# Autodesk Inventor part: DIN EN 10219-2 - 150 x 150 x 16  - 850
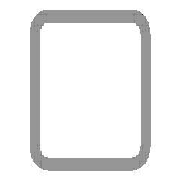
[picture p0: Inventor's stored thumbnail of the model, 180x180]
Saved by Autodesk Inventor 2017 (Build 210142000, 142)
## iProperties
Created: 2017-11
Part Number: DIN EN 10219-2 - 150 x 150 x 16  - 850
Material: Steel, Mild
Description: Cold formed welded structural hollow sections of non-alloy and fine grain structural steel
Document SubType Name: Modeling
Standard: DIN
Designer: iusti
Standard Revision: 2006-07
Standards Organization: DIN
Language: en-US
Size Designation: 150 x 150 x 16
Categories: <MemberInstance><Categories><Category DisplayName="Structural Shapes" InternalName="089c4875-fa83-4c05-b084-43b9cc11f5ed" Mnemonic="GRDR"><CategoryParameter Dis
Stock Number: 150 x 150 x 16
Mass: 49891.9 g
Surface Area: 8094.11 cm^2
Volume: 6355.65 cm^3
Density: 7.85 g/cm^3
Appearance: Semi-Polished
_CCFamilyMember: 76
_CCFamilyDisplayName: DIN EN 10219-2 (Square Hollow Section - Cold Formed) - Cold formed welded structural hollow sections of non-alloy and fine grain structural steel
_FrameMemberDoc: Frame Member File
_Version: 15.0.0
_GetPNFromCC: 1
IsCustomPart: 1
G_L: 850.000 mm
G_W: 150.000 mm
G_H: 150.000 mm
+6F84F5FA-068B-4035-A374-AD197C67666E+CUTDETAIL1: Cut
+D4A8A2DA-C34A-4EF5-ADA6-744FAFA5DC9C+CUTDETAIL2: Cut
Author: iusti
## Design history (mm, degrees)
node "Start plane"
node "End plane"
sketch "Sketch"
  geometry: L1 (-75, -27)-(-75, 27); L2 (-27, 75)-(27, 75); L3 (75, 27)-(75, -27); L4 (27, -75)-(-27, -75); L5 (-27, 59)-(27, 59); L6 (59, 27)-(59, -27); L7 (27, -59)-(-27, -59); L8 (-59, -27)-(-59, 27); L9 (0, 118.918)-(0, -118.918) reference; L10 (-118.918, 0)-(118.918, 0) reference; A1 r 48 centre (-27, -27) between (-75, -27) and (-27, -75); A2 r 48 centre (-27, 27) between (-27, 75) and (-75, 27); A3 r 48 centre (27, 27) between (75, 27) and (27, 75); A4 r 48 centre (27, -27) between (27, -75) and (75, -27); A5 r 32 centre (-27, 27) between (-27, 59) and (-59, 27); A6 r 32 centre (27, 27) between (59, 27) and (27, 59); A7 r 32 centre (27, -27) between (27, -59) and (59, -27); A8 r 32 centre (-27, -27) between (-59, -27) and (-27, -59)
  constraints: 16 end point, 16 point on circle, 8 centre point, 8 tangent, 4 parallel, 3 equal radius, 2 perpendicular, 7 other
  dimensions: "d7" = 48 radius of A1 (= G_IR); "d10" = 150 distance between parallel lines of L2 L4 (= G_H); "d11" = 150 distance between parallel lines of L1 L3 (= G_W); "d12" = 16 distance between parallel lines of L3 L6 (= G_T); "d15" = 75 distance between parallel lines of L2 L10 (= 0.5 x d10); "d16" = 75 distance between parallel lines of L9 L3 (= 0.5 x d11)
extrude "Body" new body sketch "Sketch" stored distance "d3" = 850 (= G_L); taper "d4" = 0 deg
node "Driven Length"
  sketch "Sketch3"
    geometry: L1 (0, 0)-(10, 0) reference
    constraints: 2 end point, 1 horizontal
  workplane "Work Plane3"
  sketch "Sketch4"
    geometry: L1 (-2, 75)-(12, 75) reference; L2 (-2, 925)-(12, 925) reference
    dimensions: "d18" = 850 distance between parallel lines of L1 L2 (derived)
workplane "Work Plane4"
split "Split1"
workplane "Work Plane5"
split "Split2"
body "Solid1"
other parameters: "G_W" = 150 [user parameter; used in 1 equation term], "G_H" = 150 [user parameter; used in 1 equation term], "G_T" = 16 [user parameter; used in 1 equation term], "G_IR" = 48 [user parameter; used in 1 equation term], "G_L" = 850 (= d18) [user parameter; used in 1 equation term], "G_OFFSET_START" = -75 [user parameter; used in 1 equation term], "G_OFFSET_END" = -75 [user parameter; used in 1 equation term], "d13" = 75 (= -G_OFFSET_START), "d14" = 925 (= G_OFFSET_END + B_L), "d17" = 90 deg
